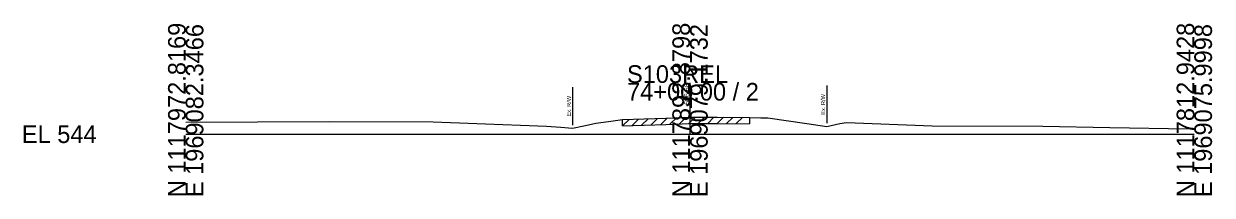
# Model space of a CAD drawing. Extents: x -26 to 163, y -10 to 24518.
# Drawn here: x -25.7 to 162.8, y 22490.3 to 22517.5 of the extents above; entities that cross this region are included whole.
import ezdxf

# ---------------------------------------------------------------- set-up
doc = ezdxf.new("R2010")
doc.units = 0
for name, color, linetype in [('RD_GPK_XS_Cell', 7, 'Continuous'), ('RD_XS_ExGround', 7, 'Continuous'), ('RD_XS_ExPaveRet', 7, 'Continuous'), ('RD_XS_ExRW', 7, 'Continuous'), ('RD_XS_TX_Elev_EX', 7, 'Continuous')]:
    doc.layers.add(name, color=color, linetype=linetype)

msp = doc.modelspace()

# ---------------------------------------------------------------- linework, layer by layer
at = {"layer": 'RD_GPK_XS_Cell'}
for p, q in [((80, 22500), (80, 22508.14)), ((0, 22500), (80, 22500)), ((80, 22500), (160, 22500))]:
    msp.add_line(p, q, dxfattribs=at)
at = {"layer": 'RD_XS_ExGround'}
msp.add_lwpolyline([(0, 22501.92), (22.77, 22501.99), (39.25, 22501.96), (46.19, 22501.7), (57.25, 22501.29), (59.49, 22501.13), (61.36, 22500.95), (63.44, 22501.38), (65.07, 22501.75), (67.04, 22502.02), (69.31, 22502.31), (76.17, 22502.54), (80, 22502.68), (81.05, 22502.71), (84.31, 22502.68), (89.45, 22502.66), (91.24, 22502.6), (92.33, 22502.57), (98.54, 22501.68), (101.68, 22501.23), (103.75, 22501.68), (104.83, 22501.87), (118.43, 22501.32), (135.95, 22501.27), (146.59, 22501.06), (159.02, 22500.83)], dxfattribs=at)
at = {"layer": 'RD_XS_ExPaveRet'}
for p, q in [((69.31, 22501.31), (70.35, 22502.35)), ((69.31, 22501.31), (69.31, 22502.31)), ((69.31, 22501.31), (76.17, 22501.54)), ((70.81, 22501.36), (71.85, 22502.4)), ((72.31, 22501.41), (73.35, 22502.45)), ((73.81, 22501.46), (74.85, 22502.5)), ((75.31, 22501.51), (76.35, 22502.55)), ((76.17, 22501.54), (80, 22501.68)), ((76.81, 22501.57), (77.85, 22502.6)), ((78.31, 22501.62), (79.35, 22502.65)), ((79.81, 22501.67), (80.85, 22502.71)), ((80, 22501.68), (81.05, 22501.71)), ((81.05, 22501.71), (84.31, 22501.68)), ((81.31, 22501.71), (82.3, 22502.7)), ((82.81, 22501.7), (83.8, 22502.69)), ((84.31, 22501.68), (85.31, 22502.68)), ((84.31, 22501.68), (89.45, 22501.66)), ((85.81, 22501.67), (86.81, 22502.67)), ((87.31, 22501.67), (88.31, 22502.66)), ((89.45, 22502.66), (89.45, 22501.66))]:
    msp.add_line(p, q, dxfattribs=at)
at = {"layer": 'RD_XS_ExRW'}
for p, q in [((61.36, 22507.45), (61.36, 22501.45)), ((101.68, 22507.73), (101.68, 22501.73))]:
    msp.add_line(p, q, dxfattribs=at)

# ---------------------------------------------------------------- texts
at = {"layer": 'RD_GPK_XS_Cell'}
for s, p in [('N 1117972.8169', (0, 22490)), ('E 1969082.3466', (2.8, 22490)), ('N 1117892.8798', (80, 22490)), ('E 1969079.1732', (82.8, 22490)), ('N 1117812.9428', (160, 22490)), ('E 1969075.9998', (162.8, 22490))]:
    msp.add_text(s, height=2.8, rotation=90, dxfattribs=at).set_placement(p)
for s, p in [('S103REL', (70, 22508.14)), ('74+00.00 / 2', (70, 22505.34)), ('EL 544', (-26, 22498.6))]:
    msp.add_text(s, height=2.8, dxfattribs=at).set_placement(p)
at = {"layer": 'RD_XS_ExRW'}
for p in [(61.11, 22502.79), (101.43, 22503.07)]:
    msp.add_text('Ex. R/W ', height=0.65, rotation=90, dxfattribs=at).set_placement(p)
at = {"layer": 'RD_XS_TX_Elev_EX'}
msp.add_text('546.68', height=0.8, rotation=90, dxfattribs=at).set_placement((79.9, 22504.68))

doc.saveas('drawing.dxf')
